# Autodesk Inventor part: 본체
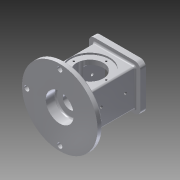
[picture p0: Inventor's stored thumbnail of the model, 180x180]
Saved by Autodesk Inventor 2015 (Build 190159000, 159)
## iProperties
Created: 2019-08
Part Number: 본체
Material: 알루미늄 6061
Document SubType Name: Modeling
Designer: a-20
Density: 2.7 g/cm^3
Appearance: 알루미늄 - 평지
Mass: 1023 g
Surface Area: 817.999 cm^2
Volume: 378.89 cm^3
Author: a-20
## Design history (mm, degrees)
sketch "스케치1"
  geometry: L1 (37, 33)-(-37, 33); L2 (-37, 33)-(-37, -33); L3 (-37, -33)-(37, -33); L4 (37, -33)-(37, 33); L5 (37, 33)-(-37, -33); 2 further points
  constraints: 10 end point, 2 parallel, 1 coincident, 1 horizontal, 1 midpoint, 1 perpendicular
  dimensions: "d0" = 66 distance of L3.end L1.start; "d1" = 74 distance of L1.start L1.end
extrude "돌출1" new body sketch "스케치1" stored distance "d2" = 108; taper "d3" = 0 deg
sketch "스케치2"
  geometry: L1 (0, 57.453)-(0, -57.453); L2 (0, 33)-(35, 33); L3 (35, 33)-(35, 30); L4 (35, 30)-(24, 30); L5 (24, 30)-(24, -30); L6 (24, -30)-(35, -30); L7 (35, -30)-(35, -33); L8 (35, -33)-(0, -33); 2 further points
  constraints: 16 end point, 5 perpendicular, 4 point on line, 1 coincident, 1 horizontal, 1 midpoint, 1 vertical
  dimensions: "d4" = 70 diameter of L3 L1; "d5" = 48 diameter of L5 L1; "d7" = 33 distance from line of point (0, 0) L2; "d8" = 3 distance between parallel lines of L2 L4; "d9" = 3 distance between parallel lines of L8 L6; "d84" = 66 distance between parallel lines of L8 L2
revolve "회전1" sketch "스케치2" stored, may be unused: angle "d10" = 90 deg
sketch "스케치3"
  geometry: C1 r 67.5 at (0, 0); 1 further point
  constraints: 1 centre point, 1 coincident
  dimensions: "d11" = 135 diameter of C1
extrude "돌출2" join sketch "스케치3" distance "d12" = 10; taper "d13" = 0 deg
sketch "스케치4"
  geometry: L1 (-46, -41)-(46, -41); L2 (46, -41)-(46, 41); L3 (46, 41)-(-46, 41); L4 (-46, 41)-(-46, -41); L5 (-46, -41)-(46, 41); 2 further points
  constraints: 10 end point, 2 parallel, 1 coincident, 1 horizontal, 1 midpoint, 1 perpendicular
  dimensions: "d14" = 82 distance of L3.end L1.start; "d15" = 92 distance of L1.start L1.end
extrude "돌출3" join sketch "스케치4" distance "d16" = 10; taper "d17" = 0 deg
sketch "스케치5"
  geometry: L1 (-26, -26)-(26, -26); L2 (26, -26)-(26, 26); L3 (26, 26)-(-26, 26); L4 (-26, 26)-(-26, -26); L5 (-26, -26)-(26, 26); 2 further points
  constraints: 10 end point, 2 parallel, 1 coincident, 1 horizontal, 1 midpoint, 1 perpendicular
  dimensions: "d18" = 52 distance of L3.end L1.start; "d19" = 52 distance of L2.end L3.end
extrude "돌출4" cut sketch "스케치5" distance "d20" = 8; taper "d21" = 0 deg
sketch "스케치6"
  geometry: L1 (-22, -22)-(22, -22); L2 (22, -22)-(22, 22); L3 (22, 22)-(-22, 22); L4 (-22, 22)-(-22, -22); L5 (-22, -22)-(22, 22); 2 further points
  constraints: 10 end point, 2 parallel, 1 coincident, 1 horizontal, 1 midpoint, 1 perpendicular
  dimensions: "d22" = 44 distance of L3.end L1.start; "d23" = 44 distance of L1.start L1.end
extrude "돌출5" cut sketch "스케치6" distance "d24" = 74; taper "d25" = 0 deg
sketch "스케치7"
  geometry: L1 (-64.131, 0)-(0, 0); L2 (-54, -67.5)-(-54, 67.5) reference; L3 (-54, 0)-(-54, 25); L4 (-36, 25)-(-36, 12.5); L5 (-36, 12.5)-(-20.187, 12.5); L6 (-20.187, 12.5)-(-20.187, 0); L7 (-54, 25)-(-36, 25); L8 (-20.187, 0)-(-54, 0)
  constraints: 14 end point, 2 horizontal, 2 perpendicular, 2 point on line, 1 collinear, 1 midpoint, 1 vertical
  dimensions: "d26" = 50 diameter of L7 L1; "d27" = 25 diameter of L5 L1; "d28" = 18 distance between parallel lines of L4 L2; "d29" = 33.81323 distance between parallel lines of L6 L2
revolve "회전2" sketch "스케치7" stored, may be unused: angle "d30" = 90 deg
sketch "스케치10"
  geometry: L1 (0, 0)-(0, 59)
  constraints: 2 end point, 1 vertical
  dimensions: "d51" = 59 distance of L1.start L1.end
hole "구멍3" sketch "스케치10" at (0, 59) diameter "d52" = 9; stored, may be unused: countersink angle "d56" = 90 deg, drill point angle "d58" = 118 deg; dims "d53" = 12, "d54" = 4, "d55" = 2, "d57" = 17.1
sketch "스케치11"
  geometry: L1 (-36, 31)-(36, 31); L2 (36, 31)-(36, -31); L3 (36, -31)-(-36, -31); L4 (-36, -31)-(-36, 31); L5 (-36, 31)-(36, -31); 6 further points
  constraints: 10 end point, 5 coincident, 2 parallel, 1 horizontal, 1 midpoint, 1 perpendicular
  dimensions: "d62" = 72 distance of L1.start L1.end; "d63" = 62 distance of L1.end L2.end
hole "구멍4" sketch "스케치11" at (-36, 31), (36, 31), (36, -31), (-36, -31) diameter "d64" = 3.242; stored, may be unused: countersink angle "d68" = 90 deg, drill point angle "d70" = 118 deg; dims "d65" = 4, "d66" = 4, "d67" = 2, "d69" = 6
fillet "모깎기1" dims "d71" = 10
fillet "모깎기3" dims "d73" = 3
chamfer "모따기1" distance "d74" = 3; stored, may be unused: second distance "d75" = 2, angle "d76" = 45 deg
chamfer "모따기2" distance "d77" = 1; stored, may be unused: second distance "d78" = 2, angle "d79" = 45 deg
sketch "스케치12"
  geometry: C1 r 59 at (0, 0); 1 further point
  constraints: 1 centre point, 1 coincident, 1 other
  dimensions: "d80" = 118 diameter of C1
feature "엠보싱1" sketch "스케치12" dims "d0" = 66, "d1" = 74, "d11" = 135, "d81" = 0.5, "d82" = 0
fillet "모깎기4" dims "d83" = 3
sketch "스케치13"
  geometry: L1 (34, -41)-(34, -12)
  constraints: 2 end point, 1 vertical
  dimensions: "d85" = 29 distance of L1.start L1.end
hole "구멍5" sketch "스케치13" at (34, -12) diameter "d86" = 3.242; stored, may be unused: countersink angle "d90" = 90 deg, drill point angle "d92" = 118 deg; dims "d87" = 7, "d88" = 4, "d89" = 2, "d91" = 9
sketch "스케치14"
  geometry: L1 (55, -10)-(5, -10) reference; L2 (30, 44)-(30, 70); L3 (30, 44)-(30, 27)
  constraints: 4 end point, 2 vertical
  dimensions: "d96" = 37 distance from line of L1 L3.end; "d97" = 43 distance of L2.end L3.end
hole "구멍6" sketch "스케치14" at (30, 70), (30, 27) diameter "d98" = 4.917; stored, may be unused: countersink angle "d102" = 90 deg, drill point angle "d104" = 118 deg; dims "d99" = 12, "d100" = 4, "d101" = 2, "d103" = 17.1
node "솔리드1"
pattern_circular "원형 패턴2" dims angle "d60" = -180 deg
pattern_circular "원형 패턴3" dims angle "d94" = 360 deg
mirror "대칭3"
mirror "대칭4"
